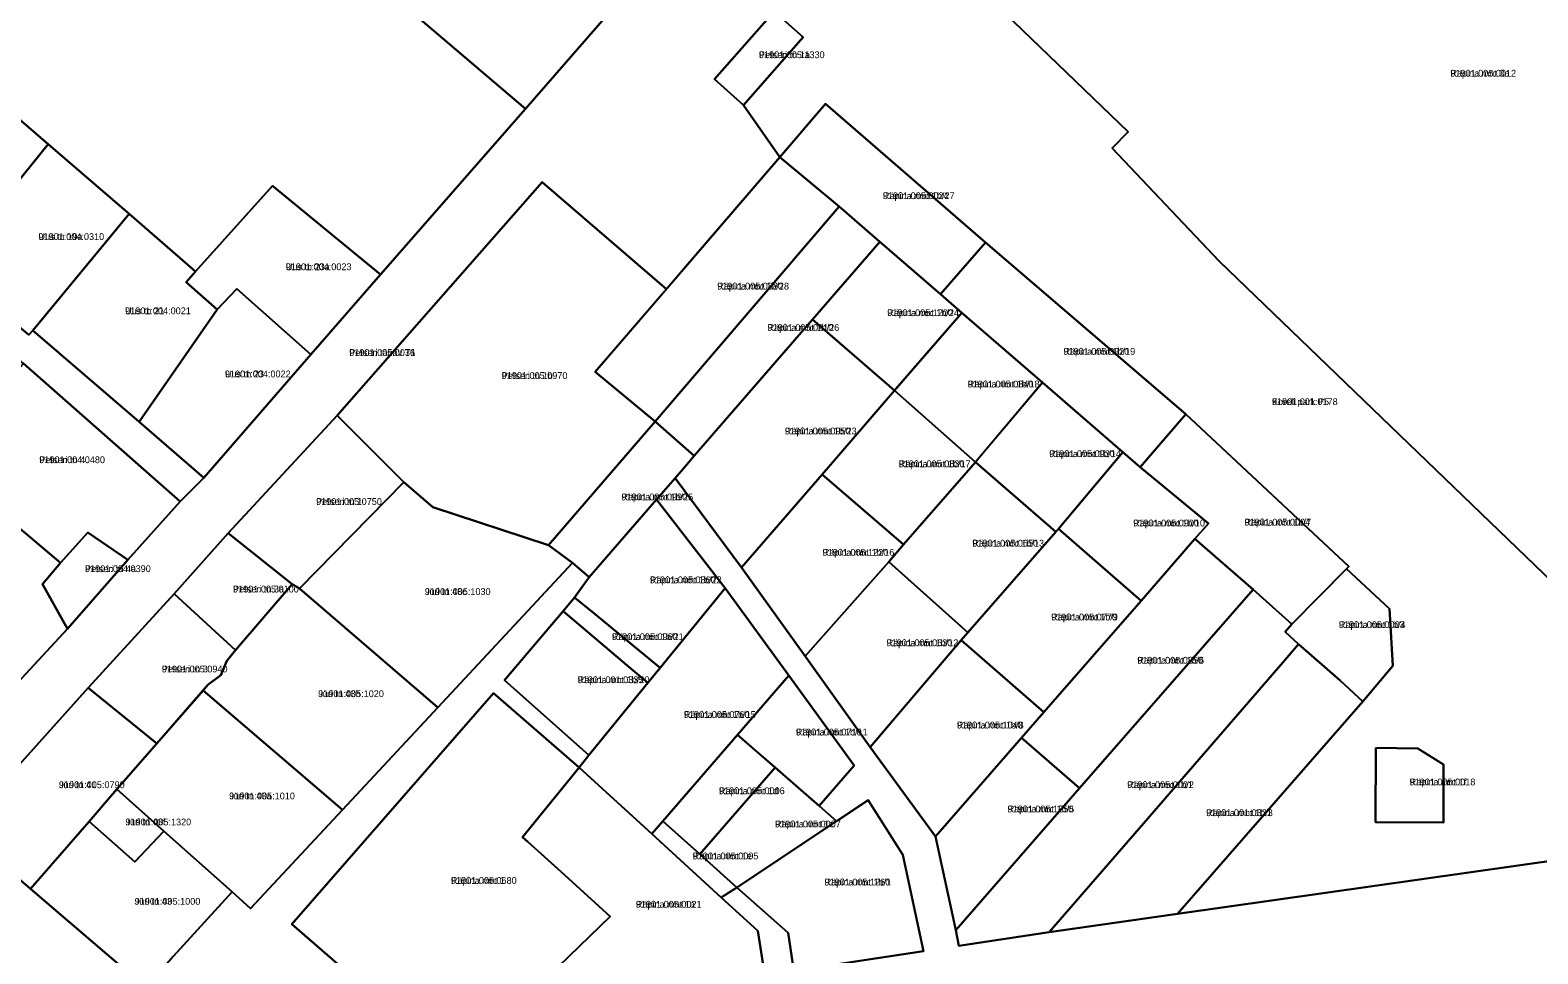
# Model space of a CAD drawing. Extents: x 675810 to 681273, y 6411190 to 6417565.
# Drawn here: x 678420.5 to 678753.1, y 6415229.9 to 6415433.8 of the extents above; entities that cross this region are included whole.
import ezdxf

# ---------------------------------------------------------------- set-up
doc = ezdxf.new("R2010")
doc.units = 0
for name, color, linetype in [('L_AADRESS', 7, 'Continuous'), ('PIIR', 7, 'Continuous'), ('TUNNUS', 7, 'Continuous')]:
    doc.layers.add(name, color=color, linetype=linetype)

msp = doc.modelspace()

# ---------------------------------------------------------------- linework, layer by layer
at = {"layer": 'PIIR'}
for points in [[(678788.36, 6415281.11), (678682.83, 6415382.78), (678659.2, 6415407.69), (678662.7, 6415411.33), (678618.06, 6415454.35), (678654.27, 6415491.95), (678689.39, 6415528.39), (678681.42, 6415550.39), (678689.11, 6415558.37), (678696.36, 6415558.3), (678719.35, 6415533.64), (678746.79, 6415495.08), (678771.76, 6415471.03)], [(678582.57, 6415225.11), (678581.03, 6415234.94), (678572.95, 6415242.31), (678576.41, 6415244.55), (678587.69, 6415234.52), (678588.94, 6415226.11), (678617.59, 6415230.49), (678613.01, 6415251.72), (678605.36, 6415263.8), (678598.42, 6415259.18), (678594.56, 6415262.52), (678602.32, 6415271.45), (678587.84, 6415291.32), (678573.84, 6415310.56), (678558.68, 6415330.15), (678562.77, 6415334.88), (678577.43, 6415315.18), (678591.46, 6415295.54), (678605.8, 6415275.49), (678620.21, 6415255.8), (678624.68, 6415235.06), (678625.41, 6415231.66), (678645.33, 6415234.64), (678673.64, 6415238.7), (678802.18, 6415256.98)], [(678452, 6415229.25), (678465.03, 6415243.56), (678469.13, 6415239.91), (678489.37, 6415261.63), (678510.41, 6415284.21), (678540.15, 6415316.14), (678543.8, 6415312.98), (678540.61, 6415308.56), (678538.08, 6415305.53), (678525.1, 6415290.28), (678543.71, 6415273.72), (678541.59, 6415271.02), (678522.69, 6415287.38), (678478.18, 6415236.44), (678505.53, 6415212.72)], [(678405.25, 6415257.4), (678420.55, 6415244.19), (678446.11, 6415222.34)]]:
    msp.add_lwpolyline(points, dxfattribs=at)
for points in [[(678529.76, 6415416.4), (678434.11, 6415497.88), (678475.9, 6415544.38), (678556.91, 6415466.12), (678565.67, 6415457.65)], [(678434.11, 6415497.88), (678529.76, 6415416.4), (678497.75, 6415379.78), (678473.98, 6415399.41), (678456.97, 6415380.5), (678442.3, 6415393.23), (678424.47, 6415408.59), (678402.71, 6415427.34), (678384.39, 6415443.11), (678370.48, 6415455.37), (678368.05, 6415457.5), (678381.04, 6415471.59), (678389.48, 6415480.64), (678405.4, 6415465.9)], [(678273.27, 6415478.75), (678277.87, 6415483.96), (678287.12, 6415475.58), (678289.51, 6415473.6), (678306.27, 6415458.37), (678324.85, 6415442.44), (678345.13, 6415426.1), (678359.84, 6415414.24), (678360.85, 6415415.07), (678379.07, 6415399.51), (678402.32, 6415381.22), (678420.16, 6415366.53), (678421.09, 6415367.45), (678444.52, 6415347.27), (678458.78, 6415334.97), (678453.58, 6415329.69), (678419.02, 6415360.14), (678398.21, 6415377.65), (678344.96, 6415419.46), (678326.53, 6415433.78), (678308.66, 6415448.56), (678290.99, 6415463.75)], [(678584.63, 6415437.83), (678608.76, 6415463.31), (678618.06, 6415454.35), (678662.7, 6415411.33), (678659.2, 6415407.69), (678682.83, 6415382.78), (678788.36, 6415281.11), (678802.18, 6415256.98), (678673.64, 6415238.7), (678714.53, 6415285.6), (678721.11, 6415293.41), (678720.4, 6415306.05), (678710.92, 6415314.87), (678711.4, 6415315.4), (678675.46, 6415348.99), (678631.26, 6415386.89), (678595.98, 6415417.47), (678585.87, 6415405.7), (678577.83, 6415417.22), (678591.06, 6415432.23)], [(678565.67, 6415457.65), (678584.63, 6415437.83), (678571.47, 6415422.91), (678577.83, 6415417.22), (678585.87, 6415405.7), (678566.01, 6415382.6), (678560.85, 6415376.6), (678533.42, 6415400.18), (678488.18, 6415348.7), (678464.2, 6415322.7), (678452.22, 6415309.34), (678433.25, 6415288.62), (678405.25, 6415257.4), (678395.92, 6415265.33), (678410.29, 6415281.72), (678428.69, 6415301.59), (678442, 6415316.83), (678453.58, 6415329.69), (678458.78, 6415334.97), (678482.4, 6415362.13), (678497.75, 6415379.78), (678529.76, 6415416.4)], [(678571.47, 6415422.91), (678584.63, 6415437.83), (678591.06, 6415432.23), (678577.83, 6415417.22)], [(678402.71, 6415427.34), (678424.47, 6415408.59), (678402.32, 6415381.22), (678379.07, 6415399.51)], [(678595.98, 6415417.47), (678631.26, 6415386.89), (678621.35, 6415375.46), (678607.96, 6415387.04), (678599.01, 6415394.8), (678585.87, 6415405.7)], [(678442.3, 6415393.23), (678421.09, 6415367.45), (678420.16, 6415366.53), (678402.32, 6415381.22), (678424.47, 6415408.59)], [(678558.36, 6415347.35), (678545.13, 6415358.32), (678566.01, 6415382.6), (678585.87, 6415405.7), (678599.01, 6415394.8)], [(678454.91, 6415378.15), (678456.97, 6415380.5), (678473.98, 6415399.41), (678497.75, 6415379.78), (678482.4, 6415362.13), (678466.05, 6415376.68), (678461.76, 6415372.06)], [(678488.18, 6415348.7), (678533.42, 6415400.18), (678560.85, 6415376.6), (678545.13, 6415358.32), (678558.36, 6415347.35), (678534.87, 6415320.06), (678509.29, 6415328.47), (678502.95, 6415333.95)], [(678593.11, 6415369.89), (678592.56, 6415369.27), (678567.01, 6415339.76), (678558.36, 6415347.35), (678599.01, 6415394.8), (678607.96, 6415387.04)], [(678421.09, 6415367.45), (678442.3, 6415393.23), (678456.97, 6415380.5), (678454.91, 6415378.15), (678461.76, 6415372.06), (678444.52, 6415347.27)], [(678612, 6415355.16), (678611.2, 6415354.22), (678593.11, 6415369.89), (678607.96, 6415387.04), (678621.35, 6415375.46), (678626.05, 6415371.37)], [(678631.26, 6415386.89), (678675.46, 6415348.99), (678665.39, 6415337.31), (678661.57, 6415340.61), (678643.82, 6415355.98), (678626.05, 6415371.37), (678621.35, 6415375.46)], [(678444.52, 6415347.27), (678461.76, 6415372.06), (678466.05, 6415376.68), (678482.4, 6415362.13), (678458.78, 6415334.97)], [(678629.03, 6415338.41), (678611.2, 6415354.22), (678626.05, 6415371.37), (678643.82, 6415355.98)], [(678611.2, 6415354.22), (678595.2, 6415335.69), (678577.43, 6415315.18), (678562.77, 6415334.88), (678564.62, 6415337), (678567.01, 6415339.76), (678592.56, 6415369.27), (678593.11, 6415369.89)], [(678400.18, 6415338.89), (678419.02, 6415360.14), (678453.58, 6415329.69), (678442, 6415316.83), (678433.19, 6415322.87), (678427.17, 6415316.21)], [(678375, 6415312.11), (678352.05, 6415330.57), (678368.95, 6415350.58), (678379.53, 6415356.26), (678400.18, 6415338.89), (678427.17, 6415316.21), (678423.18, 6415311.45), (678428.69, 6415301.59), (678410.29, 6415281.72)], [(678629.03, 6415338.41), (678613.19, 6415320.22), (678595.2, 6415335.69), (678611.2, 6415354.22)], [(678647.38, 6415323.7), (678646.8, 6415323.04), (678629.03, 6415338.41), (678629.82, 6415339.36), (678643.82, 6415355.98), (678661.57, 6415340.61)], [(678502.95, 6415333.95), (678479.92, 6415310.49), (678478.27, 6415311.46), (678464.2, 6415322.7), (678488.18, 6415348.7)], [(678564.62, 6415337), (678562.77, 6415334.88), (678558.68, 6415330.15), (678543.8, 6415312.98), (678540.15, 6415316.14), (678534.87, 6415320.06), (678558.36, 6415347.35), (678567.01, 6415339.76)], [(678665.39, 6415337.31), (678675.46, 6415348.99), (678711.4, 6415315.4), (678710.92, 6415314.87), (678698.88, 6415302.64), (678690.28, 6415310.26), (678677.47, 6415321.44), (678680.43, 6415324.84)], [(678661.57, 6415340.61), (678665.39, 6415337.31), (678680.43, 6415324.84), (678677.47, 6415321.44), (678665.59, 6415307.82), (678647.38, 6415323.7)], [(678609.91, 6415316.36), (678613.19, 6415320.22), (678629.03, 6415338.41), (678646.8, 6415323.04), (678627.39, 6415300.78)], [(678509.29, 6415328.47), (678534.87, 6415320.06), (678540.15, 6415316.14), (678510.41, 6415284.21), (678479.92, 6415310.49), (678502.95, 6415333.95)], [(678595.2, 6415335.69), (678613.19, 6415320.22), (678609.91, 6415316.36), (678591.46, 6415295.54), (678577.43, 6415315.18)], [(678573.84, 6415310.56), (678559.5, 6415292.99), (678554.9, 6415296.78), (678545.19, 6415304.79), (678540.61, 6415308.56), (678543.8, 6415312.98), (678558.68, 6415330.15)], [(678428.69, 6415301.59), (678423.18, 6415311.45), (678427.17, 6415316.21), (678433.19, 6415322.87), (678442, 6415316.83)], [(678464.2, 6415322.7), (678478.27, 6415311.46), (678465.81, 6415296.87), (678452.22, 6415309.34)], [(678644.12, 6415283.21), (678625.91, 6415299.09), (678627.39, 6415300.78), (678646.8, 6415323.04), (678647.38, 6415323.7), (678665.59, 6415307.82)], [(678690.28, 6415310.26), (678652.02, 6415266.41), (678639.21, 6415277.58), (678644.12, 6415283.21), (678665.59, 6415307.82), (678677.47, 6415321.44)], [(678627.39, 6415300.78), (678625.91, 6415299.09), (678605.8, 6415275.49), (678591.46, 6415295.54), (678609.91, 6415316.36)], [(678698.88, 6415302.64), (678710.92, 6415314.87), (678720.4, 6415306.05), (678721.11, 6415293.41), (678714.53, 6415285.6), (678709.5, 6415290.17), (678700.35, 6415298.24), (678697.35, 6415300.91)], [(678465.81, 6415296.87), (678478.27, 6415311.46), (678479.92, 6415310.49), (678510.41, 6415284.21), (678489.37, 6415261.63), (678458.63, 6415288.03), (678459.69, 6415289.26), (678462.57, 6415291.38), (678463.86, 6415294.58)], [(678587.84, 6415291.32), (678576.54, 6415278.2), (678560.08, 6415259.15), (678557.65, 6415256.33), (678541.59, 6415271.02), (678543.71, 6415273.72), (678556.79, 6415289.7), (678559.5, 6415292.99), (678573.84, 6415310.56)], [(678465.81, 6415296.87), (678463.86, 6415294.58), (678462.57, 6415291.38), (678459.69, 6415289.26), (678448.41, 6415276.29), (678433.25, 6415288.62), (678452.22, 6415309.34)], [(678538.08, 6415305.53), (678540.61, 6415308.56), (678545.19, 6415304.79), (678554.9, 6415296.78), (678559.5, 6415292.99), (678556.79, 6415289.7), (678552.12, 6415293.61), (678542.44, 6415301.84)], [(678690.28, 6415310.26), (678698.88, 6415302.64), (678697.35, 6415300.91), (678700.35, 6415298.24), (678696.83, 6415294.18), (678665.14, 6415257.5), (678645.33, 6415234.64), (678625.41, 6415231.66), (678624.68, 6415235.06), (678652.02, 6415266.41)], [(678525.1, 6415290.28), (678538.08, 6415305.53), (678542.44, 6415301.84), (678552.12, 6415293.61), (678556.79, 6415289.7), (678543.71, 6415273.72)], [(678625.91, 6415299.09), (678644.12, 6415283.21), (678639.21, 6415277.58), (678620.21, 6415255.8), (678605.8, 6415275.49)], [(678696.83, 6415294.18), (678700.35, 6415298.24), (678709.5, 6415290.17), (678714.53, 6415285.6), (678673.64, 6415238.7), (678645.33, 6415234.64), (678665.14, 6415257.5)], [(678594.56, 6415262.52), (678584.84, 6415271), (678576.54, 6415278.2), (678587.84, 6415291.32), (678602.32, 6415271.45)], [(678405.25, 6415257.4), (678433.25, 6415288.62), (678448.41, 6415276.29), (678439.58, 6415266.25), (678433.48, 6415259.07), (678420.55, 6415244.19)], [(678489.37, 6415261.63), (678469.13, 6415239.91), (678465.03, 6415243.56), (678450.01, 6415256.96), (678439.58, 6415266.25), (678448.41, 6415276.29), (678458.63, 6415288.03)], [(678505.53, 6415212.72), (678478.18, 6415236.44), (678522.69, 6415287.38), (678541.59, 6415271.02), (678529.12, 6415255.64), (678530.27, 6415254.6), (678537.61, 6415247.95), (678548.45, 6415238.12), (678525.66, 6415216.01)], [(678576.54, 6415278.2), (678580.15, 6415275.06), (678584.84, 6415271), (678568.24, 6415251.89), (678560.08, 6415259.15)], [(678620.21, 6415255.8), (678639.21, 6415277.58), (678652.02, 6415266.41), (678624.68, 6415235.06)], [(678717.36, 6415275.31), (678726.65, 6415275.21), (678732.33, 6415271.66), (678732.31, 6415258.89), (678717.33, 6415258.9)], [(678717.36, 6415275.31), (678717.33, 6415258.9), (678732.31, 6415258.89), (678732.33, 6415271.66), (678726.65, 6415275.21)], [(678541.59, 6415271.02), (678557.65, 6415256.33), (678572.95, 6415242.31), (678581.03, 6415234.94), (678582.57, 6415225.11), (678525.66, 6415216.01), (678548.45, 6415238.12), (678537.61, 6415247.95), (678530.27, 6415254.6), (678529.12, 6415255.64)], [(678584.84, 6415271), (678589.58, 6415266.88), (678594.56, 6415262.52), (678598.42, 6415259.18), (678576.41, 6415244.55), (678568.24, 6415251.89)], [(678433.48, 6415259.07), (678439.58, 6415266.25), (678450.01, 6415256.96), (678443.55, 6415250.2)], [(678598.42, 6415259.18), (678605.36, 6415263.8), (678613.01, 6415251.72), (678617.59, 6415230.49), (678588.94, 6415226.11), (678587.69, 6415234.52), (678576.41, 6415244.55)], [(678420.55, 6415244.19), (678433.48, 6415259.07), (678443.55, 6415250.2), (678450.01, 6415256.96), (678465.03, 6415243.56), (678452, 6415229.25), (678446.11, 6415222.34)], [(678560.08, 6415259.15), (678568.24, 6415251.89), (678576.41, 6415244.55), (678572.95, 6415242.31), (678557.65, 6415256.33)]]:
    msp.add_lwpolyline(points, close=True, dxfattribs=at)

# ---------------------------------------------------------------- texts
at = {"layer": 'L_AADRESS'}
for s, p in [('Petseri tn 1a', (678581.27, 6415427.57)), ('Räpina mnt 3a', (678733.82, 6415423.49)), ('Räpina mnt 1b/27', (678608.61, 6415396.46)), ('Uus tn 19a', (678422.31, 6415387.43)), ('Uus tn 23a', (678476.88, 6415380.77)), ('Räpina mnt 1b/28', (678572.07, 6415376.5)), ('Uus tn 21', (678441.43, 6415371.05)), ('Räpina mnt 1b/24', (678609.58, 6415370.63)), ('Räpina mnt 1b/26', (678583.16, 6415367.36)), ('Petseri tänav T1', (678490.89, 6415361.84)), ('Räpina mnt 1b/19', (678648.46, 6415362.1)), ('Uus tn 23', (678463.46, 6415357.12)), ('Petseri tn 1b', (678524.52, 6415356.76)), ('Räpina mnt 1b/18', (678627.34, 6415354.89)), ('Koreli park P5', (678694.46, 6415351)), ('Räpina mnt 1b/23', (678586.99, 6415344.52)), ('Räpina mnt 1b/14', (678645.3, 6415339.51)), ('Petseri tn 4', (678422.49, 6415338.18)), ('Räpina mnt 1b/17', (678612.12, 6415337.28)), ('Petseri tn 1', (678483.58, 6415328.96)), ('Räpina mnt 1b/25', (678550.94, 6415329.97)), ('Räpina mnt 1b/10', (678663.85, 6415324.21)), ('Räpina mnt 1b/7', (678688.39, 6415324.4)), ('Räpina mnt 1b/13', (678628.35, 6415319.76)), ('Räpina mnt 1b/16', (678595.31, 6415317.74)), ('Petseri tn 4a', (678432.59, 6415314.13)), ('Petseri tn 3a', (678465.25, 6415309.63)), ('Jüri tn 43c', (678507.57, 6415309.08)), ('Räpina mnt 1b/22', (678557.23, 6415311.67)), ('Räpina mnt 1b/9', (678645.75, 6415303.46)), ('Räpina mnt 1b/21', (678548.84, 6415299.13)), ('Räpina mnt 1b/4', (678709.23, 6415301.78)), ('Räpina mnt 1b/12', (678609.43, 6415297.78)), ('Räpina mnt 1b/6', (678664.75, 6415293.92)), ('Petseri tn 3', (678449.53, 6415291.99)), ('Räpina mnt 1b/20', (678541.28, 6415289.62)), ('Jüri tn 43b', (678484.03, 6415286.54)), ('Räpina mnt 1b/15', (678564.72, 6415281.95)), ('Räpina mnt 1b/8', (678624.96, 6415279.61)), ('Räpina mnt 1b/11', (678589.43, 6415278.07)), ('Jüri tn 41', (678426.83, 6415266.44)), ('Räpina mnt 1b/2', (678662.52, 6415266.45)), ('Räpina mnt 1f', (678724.83, 6415267.06)), ('Jüri tn 43a', (678464.39, 6415263.97)), ('Räpina mnt 1d', (678572.46, 6415265.11)), ('Räpina mnt 1b/5', (678636.12, 6415261.1)), ('Räpina mnt 1b/3', (678679.93, 6415260.27)), ('Jüri tn 43f', (678441.51, 6415258.23)), ('Räpina mnt 1c', (678584.83, 6415257.78)), ('Räpina mnt 1e', (678566.65, 6415250.73)), ('Räpina mnt 1', (678513.32, 6415245.32)), ('Räpina mnt 1b/1', (678595.74, 6415244.96)), ('Jüri tn 43', (678443.53, 6415240.71)), ('Räpina mnt 1a', (678554.11, 6415240.06))]:
    msp.add_text(s, height=1.5, dxfattribs=at).set_placement(p)
at = {"layer": 'TUNNUS'}
for s, p in [('91901:005:1330', (678581.27, 6415427.57)), ('91901:005:0012', (678733.82, 6415423.49)), ('91901:005:0024', (678608.61, 6415396.46)), ('91901:004:0310', (678422.31, 6415387.43)), ('91901:004:0023', (678476.88, 6415380.77)), ('91901:005:0880', (678572.07, 6415376.5)), ('91901:004:0021', (678441.43, 6415371.05)), ('91901:005:1200', (678609.58, 6415370.63)), ('91901:005:0910', (678583.16, 6415367.36)), ('91901:005:0036', (678490.89, 6415361.84)), ('91901:005:0920', (678648.46, 6415362.1)), ('91901:004:0022', (678463.46, 6415357.12)), ('91901:005:0970', (678524.52, 6415356.76)), ('91901:005:0840', (678627.34, 6415354.89)), ('91901:001:0178', (678694.46, 6415351)), ('91901:005:0950', (678586.99, 6415344.52)), ('91901:005:0930', (678645.3, 6415339.51)), ('91901:004:0480', (678422.49, 6415338.18)), ('91901:005:0830', (678612.12, 6415337.28)), ('91901:005:0990', (678550.94, 6415329.97)), ('91901:005:0750', (678483.58, 6415328.96)), ('91901:005:0900', (678663.85, 6415324.21)), ('91901:005:0004', (678688.39, 6415324.4)), ('91901:005:0650', (678628.35, 6415319.76)), ('91901:005:1220', (678595.31, 6415317.74)), ('91901:004:0390', (678432.59, 6415314.13)), ('91901:005:0100', (678465.25, 6415309.63)), ('91901:005:1030', (678507.57, 6415309.08)), ('91901:005:0860', (678557.23, 6415311.67)), ('91901:005:0770', (678645.75, 6415303.46)), ('91901:005:0960', (678548.84, 6415299.13)), ('91901:005:0003', (678709.23, 6415301.78)), ('91901:005:0630', (678609.43, 6415297.78)), ('91901:005:0850', (678664.75, 6415293.92)), ('91901:005:0940', (678449.53, 6415291.99)), ('91901:001:0335', (678541.28, 6415289.62)), ('91901:005:1020', (678484.03, 6415286.54)), ('91901:005:0760', (678564.72, 6415281.95)), ('91901:005:1040', (678624.96, 6415279.61)), ('91901:005:0710', (678589.43, 6415278.07)), ('91901:005:0790', (678426.83, 6415266.44)), ('91901:005:0001', (678662.52, 6415266.45)), ('91901:005:0018', (678724.83, 6415267.06)), ('91901:005:1010', (678464.39, 6415263.97)), ('91901:005:0006', (678572.46, 6415265.11)), ('91901:005:1250', (678636.12, 6415261.1)), ('91901:001:0321', (678679.93, 6415260.27)), ('91901:005:1320', (678441.51, 6415258.23)), ('91901:005:0007', (678584.83, 6415257.78)), ('91901:005:0005', (678566.65, 6415250.73)), ('91901:005:0680', (678513.32, 6415245.32)), ('91901:005:1260', (678595.74, 6415244.96)), ('91901:005:1000', (678443.53, 6415240.71)), ('91901:005:0021', (678554.11, 6415240.06))]:
    msp.add_text(s, height=1.5, dxfattribs=at).set_placement(p)

doc.saveas('drawing.dxf')
